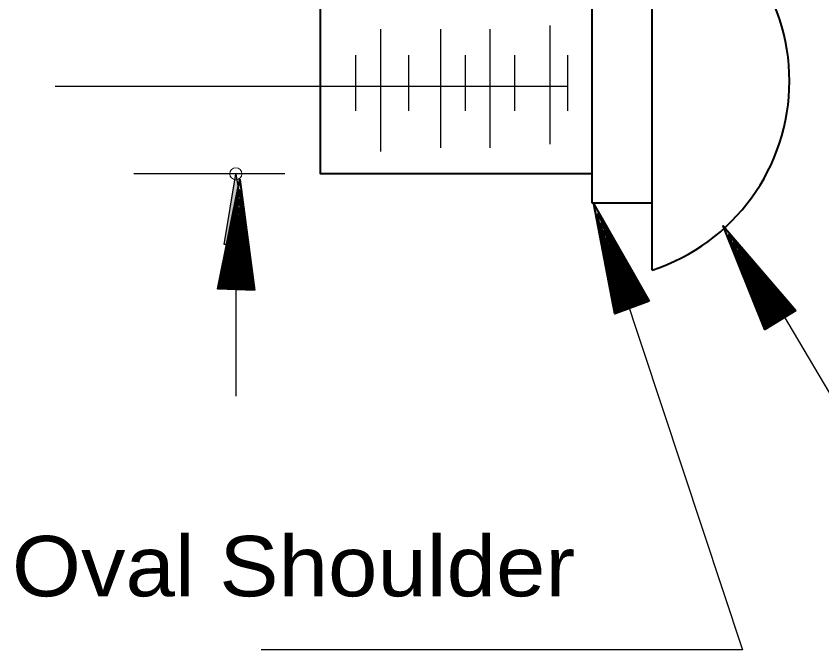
# Model space of a CAD drawing. Extents: x 895.6 to 930.4, y -2278.6 to -2254.7.
# Drawn here: x 902.343 to 904.058, y -2267.486 to -2266.136 of the extents above; entities that cross this region are included whole.
import ezdxf

# ---------------------------------------------------------------- set-up
doc = ezdxf.new("R2010")
doc.units = 0
doc.header["$LTSCALE"] = 0.051
doc.header["$PDMODE"] = 32
doc.header["$PDSIZE"] = 0.0255
for name, color, linetype, lineweight in [('1', 7, 'Continuous', 70), ('3', 7, 'Continuous', 40), ('6', 7, 'Continuous', 13)]:
    doc.layers.add(name, color=color, linetype=linetype, lineweight=lineweight)

msp = doc.modelspace()

# ---------------------------------------------------------------- hatches: boundary and pattern name
at = {"layer": '3'}
for points in [[(902.84975, -2266.71975), (902.77175, -2266.71708), (902.81867, -2266.48442), (902.81867, -2266.48442)], [(902.83533, -2266.62267), (902.78517, -2266.62267), (902.81025, -2266.472), (902.81025, -2266.472)], [(902.84583, -2266.7185), (902.77567, -2266.71617), (902.81783, -2266.50683), (902.81783, -2266.50683)], [(902.84233, -2266.7175), (902.77925, -2266.71533), (902.81725, -2266.52692), (902.81725, -2266.52692)], [(903.68983, -2266.74317), (903.61675, -2266.77033), (903.57225, -2266.53708), (903.57225, -2266.53708)], [(902.83925, -2266.7165), (902.7825, -2266.71458), (902.81667, -2266.545), (902.81667, -2266.545)], [(902.83658, -2266.71575), (902.78542, -2266.71392), (902.81617, -2266.56125), (902.81617, -2266.56125)], [(903.686, -2266.74358), (903.62, -2266.76783), (903.58, -2266.55833), (903.58, -2266.55833)], [(902.83392, -2266.71475), (902.78792, -2266.71325), (902.81567, -2266.57592), (902.81567, -2266.57592)], [(902.83158, -2266.71417), (902.79017, -2266.71283), (902.81517, -2266.58908), (902.81517, -2266.58908)], [(903.682, -2266.744), (903.623, -2266.76583), (903.587, -2266.57708), (903.587, -2266.57708)], [(904.00242, -2266.76292), (903.93608, -2266.80358), (903.84792, -2266.583), (903.84792, -2266.583)], [(902.82967, -2266.71342), (902.79233, -2266.71233), (902.81483, -2266.60108), (902.81483, -2266.60108)], [(903.67892, -2266.74425), (903.62575, -2266.76392), (903.59317, -2266.59383), (903.59317, -2266.59383)], [(903.99867, -2266.76408), (903.93883, -2266.80025), (903.85958, -2266.60225), (903.85958, -2266.60225)], [(902.82783, -2266.71308), (902.79417, -2266.71175), (902.81433, -2266.61167), (902.81433, -2266.61167)], [(902.82608, -2266.71242), (902.79575, -2266.71133), (902.81408, -2266.62133), (902.81408, -2266.62133)], [(903.67608, -2266.7445), (903.62817, -2266.76208), (903.599, -2266.60925), (903.599, -2266.60925)], [(903.67358, -2266.74442), (903.63025, -2266.7605), (903.604, -2266.62308), (903.604, -2266.62308)], [(903.99517, -2266.765), (903.94133, -2266.79783), (903.87, -2266.61925), (903.87, -2266.61925)], [(902.82458, -2266.71192), (902.79742, -2266.711), (902.81375, -2266.63), (902.81375, -2266.63)], [(902.82317, -2266.71158), (902.79883, -2266.71067), (902.81342, -2266.63775), (902.81342, -2266.63775)], [(903.67117, -2266.74483), (903.63208, -2266.75925), (903.60867, -2266.63517), (903.60867, -2266.63517)], [(903.99242, -2266.766), (903.94367, -2266.79542), (903.87925, -2266.63467), (903.87925, -2266.63467)], [(902.82208, -2266.71108), (902.8, -2266.71042), (902.81325, -2266.64492), (902.81325, -2266.64492)], [(902.82092, -2266.71067), (902.80108, -2266.71017), (902.81308, -2266.651), (902.81308, -2266.651)], [(902.82, -2266.71042), (902.80208, -2266.70983), (902.81292, -2266.65675), (902.81292, -2266.65675)], [(903.66908, -2266.74492), (903.634, -2266.75808), (903.61275, -2266.64667), (903.61275, -2266.64667)], [(903.66725, -2266.74542), (903.63558, -2266.757), (903.61625, -2266.65667), (903.61625, -2266.65667)], [(903.98958, -2266.76683), (903.94567, -2266.79325), (903.88792, -2266.64875), (903.88792, -2266.64875)], [(902.81908, -2266.71017), (902.80292, -2266.70975), (902.81258, -2266.66183), (902.81258, -2266.66183)], [(902.81825, -2266.70992), (902.80367, -2266.70942), (902.81242, -2266.66642), (902.81242, -2266.66642)], [(902.8175, -2266.70975), (902.8045, -2266.70933), (902.81233, -2266.6705), (902.81233, -2266.6705)], [(902.81708, -2266.70942), (902.80525, -2266.70917), (902.81233, -2266.67417), (902.81233, -2266.67417)], [(902.8165, -2266.70925), (902.80592, -2266.70892), (902.81225, -2266.67742), (902.81225, -2266.67742)], [(903.66542, -2266.74533), (903.63675, -2266.75575), (903.61958, -2266.66558), (903.61958, -2266.66558)], [(903.66383, -2266.74542), (903.63817, -2266.755), (903.62275, -2266.67367), (903.62275, -2266.67367)], [(903.98708, -2266.76717), (903.94742, -2266.79117), (903.8955, -2266.66133), (903.8955, -2266.66133)], [(903.98467, -2266.76808), (903.949, -2266.78967), (903.90233, -2266.67225), (903.90233, -2266.67225)], [(902.81617, -2266.709), (902.80658, -2266.70867), (902.81242, -2266.68042), (902.81242, -2266.68042)], [(902.81558, -2266.709), (902.80708, -2266.70867), (902.81225, -2266.68317), (902.81225, -2266.68317)], [(902.81508, -2266.70883), (902.8075, -2266.7085), (902.812, -2266.68558), (902.812, -2266.68558)], [(902.81483, -2266.70867), (902.808, -2266.70842), (902.81208, -2266.68775), (902.81208, -2266.68775)], [(903.66242, -2266.74575), (903.63933, -2266.75417), (903.62533, -2266.68125), (903.62533, -2266.68125)], [(903.66117, -2266.74542), (903.64042, -2266.75333), (903.62783, -2266.68767), (903.62783, -2266.68767)], [(903.66, -2266.74575), (903.64142, -2266.75267), (903.62992, -2266.69333), (903.62992, -2266.69333)], [(903.98258, -2266.7685), (903.95075, -2266.78808), (903.9085, -2266.68292), (903.9085, -2266.68292)], [(903.98075, -2266.76925), (903.952, -2266.78675), (903.914, -2266.692), (903.914, -2266.692)], [(903.659, -2266.74575), (903.64208, -2266.75217), (903.632, -2266.69892), (903.632, -2266.69892)], [(903.65808, -2266.74608), (903.64267, -2266.7515), (903.63367, -2266.70375), (903.63367, -2266.70375)], [(903.65725, -2266.74608), (903.64358, -2266.75108), (903.63517, -2266.70792), (903.63517, -2266.70792)], [(903.65642, -2266.746), (903.64433, -2266.75083), (903.6365, -2266.71175), (903.6365, -2266.71175)], [(903.97892, -2266.76975), (903.95283, -2266.78533), (903.91892, -2266.7), (903.91892, -2266.7)], [(903.97742, -2266.77), (903.95408, -2266.78425), (903.92342, -2266.70733), (903.92342, -2266.70733)], [(903.65583, -2266.74592), (903.64467, -2266.75033), (903.63825, -2266.71508), (903.63825, -2266.71508)], [(903.65525, -2266.74617), (903.64517, -2266.74967), (903.63908, -2266.71825), (903.63908, -2266.71825)], [(903.65492, -2266.746), (903.64575, -2266.74942), (903.64042, -2266.721), (903.64042, -2266.721)], [(903.65442, -2266.746), (903.64625, -2266.74917), (903.64142, -2266.72367), (903.64142, -2266.72367)], [(903.65383, -2266.74608), (903.6465, -2266.74883), (903.64208, -2266.726), (903.64208, -2266.726)], [(903.65358, -2266.74617), (903.64683, -2266.74833), (903.643, -2266.72783), (903.643, -2266.72783)], [(903.97617, -2266.7705), (903.95517, -2266.78325), (903.9275, -2266.7145), (903.9275, -2266.7145)], [(903.97492, -2266.7705), (903.95617, -2266.78217), (903.93117, -2266.72008), (903.93117, -2266.72008)], [(903.97383, -2266.77117), (903.957, -2266.78142), (903.93425, -2266.72542), (903.93425, -2266.72542)], [(903.97292, -2266.77125), (903.9575, -2266.78083), (903.93733, -2266.73042), (903.93733, -2266.73042)], [(903.97208, -2266.77158), (903.95783, -2266.78), (903.93992, -2266.73483), (903.93992, -2266.73483)], [(903.97133, -2266.772), (903.95858, -2266.77933), (903.94217, -2266.73867), (903.94217, -2266.73867)], [(903.9705, -2266.772), (903.95933, -2266.77908), (903.94425, -2266.74225), (903.94425, -2266.74225)], [(903.96992, -2266.77208), (903.95967, -2266.7785), (903.94667, -2266.745), (903.94667, -2266.745)], [(903.96933, -2266.77242), (903.96008, -2266.77775), (903.948, -2266.74817), (903.948, -2266.74817)], [(903.969, -2266.77233), (903.96058, -2266.77742), (903.94992, -2266.7505), (903.94992, -2266.7505)], [(903.9685, -2266.77242), (903.96108, -2266.77708), (903.95133, -2266.75283), (903.95133, -2266.75283)], [(903.96792, -2266.7725), (903.96125, -2266.77667), (903.9525, -2266.755), (903.9525, -2266.755)], [(903.96767, -2266.77258), (903.96142, -2266.77608), (903.95367, -2266.75683), (903.95367, -2266.75683)]]:
    msp.add_hatch(color=256, dxfattribs=at).paths.add_polyline_path(points)

# ---------------------------------------------------------------- linework, layer by layer
at = {"layer": '1', "lineweight": 40}
for p, q in [((903.69675, -2266.677), (903.69675, -2265.8725)), ((903.56908, -2266.53492), (903.56908, -2266.03817)), ((903.69675, -2266.53492), (903.56908, -2266.53492))]:
    msp.add_line(p, q, dxfattribs=at)
at = {"layer": '1', "lineweight": 25}
for p, q in [((903.47867, -2266.15658), (903.47867, -2266.40892)), ((903.118, -2266.16442), (903.118, -2266.42458)), ((903.24583, -2266.16442), (903.24583, -2266.41658)), ((903.351, -2266.16442), (903.351, -2266.41658)), ((903.06533, -2266.21967), (903.06533, -2266.33783)), ((903.17817, -2266.21967), (903.17817, -2266.33783)), ((903.2985, -2266.21967), (903.2985, -2266.33783)), ((903.40375, -2266.21967), (903.40375, -2266.33783)), ((903.51633, -2266.21967), (903.51633, -2266.33783))]:
    msp.add_line(p, q, dxfattribs=at)
at = {"layer": '1', "lineweight": 40}
msp.add_lwpolyline([(903.56908, -2266.472), (902.99017, -2266.472), (902.99017, -2266.10133)], dxfattribs=at)
msp.add_arc((903.56587, -2266.27472), 0.42298, 288.02436, 71.97563, dxfattribs=at)
at = {"layer": '3', "lineweight": 25}
for p, q in [((903.51633, -2266.28658), (902.4255, -2266.28658)), ((902.91483, -2266.472), (902.59342, -2266.472)), ((902.81025, -2266.62267), (902.81025, -2266.94517))]:
    msp.add_line(p, q, dxfattribs=at)
at = {"layer": '3'}
for points in [[(902.84975, -2266.71975), (902.77175, -2266.71708), (902.81867, -2266.48442), (902.81867, -2266.48442)], [(902.84583, -2266.7185), (902.77567, -2266.71617), (902.81783, -2266.50683), (902.81783, -2266.50683)], [(902.84233, -2266.7175), (902.77925, -2266.71533), (902.81725, -2266.52692), (902.81725, -2266.52692)], [(903.68983, -2266.74317), (903.61675, -2266.77033), (903.57225, -2266.53708), (903.57225, -2266.53708)], [(902.83925, -2266.7165), (902.7825, -2266.71458), (902.81667, -2266.545), (902.81667, -2266.545)], [(902.83658, -2266.71575), (902.78542, -2266.71392), (902.81617, -2266.56125), (902.81617, -2266.56125)], [(903.686, -2266.74358), (903.62, -2266.76783), (903.58, -2266.55833), (903.58, -2266.55833)], [(902.83392, -2266.71475), (902.78792, -2266.71325), (902.81567, -2266.57592), (902.81567, -2266.57592)], [(902.83158, -2266.71417), (902.79017, -2266.71283), (902.81517, -2266.58908), (902.81517, -2266.58908)], [(903.682, -2266.744), (903.623, -2266.76583), (903.587, -2266.57708), (903.587, -2266.57708)], [(904.00242, -2266.76292), (903.93608, -2266.80358), (903.84792, -2266.583), (903.84792, -2266.583)], [(902.82967, -2266.71342), (902.79233, -2266.71233), (902.81483, -2266.60108), (902.81483, -2266.60108)], [(903.67892, -2266.74425), (903.62575, -2266.76392), (903.59317, -2266.59383), (903.59317, -2266.59383)], [(903.99867, -2266.76408), (903.93883, -2266.80025), (903.85958, -2266.60225), (903.85958, -2266.60225)], [(902.82783, -2266.71308), (902.79417, -2266.71175), (902.81433, -2266.61167), (902.81433, -2266.61167)], [(902.82608, -2266.71242), (902.79575, -2266.71133), (902.81408, -2266.62133), (902.81408, -2266.62133)], [(903.67608, -2266.7445), (903.62817, -2266.76208), (903.599, -2266.60925), (903.599, -2266.60925)], [(903.67358, -2266.74442), (903.63025, -2266.7605), (903.604, -2266.62308), (903.604, -2266.62308)], [(903.99517, -2266.765), (903.94133, -2266.79783), (903.87, -2266.61925), (903.87, -2266.61925)], [(902.82458, -2266.71192), (902.79742, -2266.711), (902.81375, -2266.63), (902.81375, -2266.63)], [(902.82317, -2266.71158), (902.79883, -2266.71067), (902.81342, -2266.63775), (902.81342, -2266.63775)], [(903.67117, -2266.74483), (903.63208, -2266.75925), (903.60867, -2266.63517), (903.60867, -2266.63517)], [(903.99242, -2266.766), (903.94367, -2266.79542), (903.87925, -2266.63467), (903.87925, -2266.63467)], [(902.82208, -2266.71108), (902.8, -2266.71042), (902.81325, -2266.64492), (902.81325, -2266.64492)], [(902.82092, -2266.71067), (902.80108, -2266.71017), (902.81308, -2266.651), (902.81308, -2266.651)], [(902.82, -2266.71042), (902.80208, -2266.70983), (902.81292, -2266.65675), (902.81292, -2266.65675)], [(903.66908, -2266.74492), (903.634, -2266.75808), (903.61275, -2266.64667), (903.61275, -2266.64667)], [(903.66725, -2266.74542), (903.63558, -2266.757), (903.61625, -2266.65667), (903.61625, -2266.65667)], [(903.98958, -2266.76683), (903.94567, -2266.79325), (903.88792, -2266.64875), (903.88792, -2266.64875)], [(902.81908, -2266.71017), (902.80292, -2266.70975), (902.81258, -2266.66183), (902.81258, -2266.66183)], [(902.81825, -2266.70992), (902.80367, -2266.70942), (902.81242, -2266.66642), (902.81242, -2266.66642)], [(902.8175, -2266.70975), (902.8045, -2266.70933), (902.81233, -2266.6705), (902.81233, -2266.6705)], [(902.81708, -2266.70942), (902.80525, -2266.70917), (902.81233, -2266.67417), (902.81233, -2266.67417)], [(902.8165, -2266.70925), (902.80592, -2266.70892), (902.81225, -2266.67742), (902.81225, -2266.67742)], [(903.66542, -2266.74533), (903.63675, -2266.75575), (903.61958, -2266.66558), (903.61958, -2266.66558)], [(903.66383, -2266.74542), (903.63817, -2266.755), (903.62275, -2266.67367), (903.62275, -2266.67367)], [(903.98708, -2266.76717), (903.94742, -2266.79117), (903.8955, -2266.66133), (903.8955, -2266.66133)], [(903.98467, -2266.76808), (903.949, -2266.78967), (903.90233, -2266.67225), (903.90233, -2266.67225)], [(902.81617, -2266.709), (902.80658, -2266.70867), (902.81242, -2266.68042), (902.81242, -2266.68042)], [(902.81558, -2266.709), (902.80708, -2266.70867), (902.81225, -2266.68317), (902.81225, -2266.68317)], [(902.81508, -2266.70883), (902.8075, -2266.7085), (902.812, -2266.68558), (902.812, -2266.68558)], [(902.81483, -2266.70867), (902.808, -2266.70842), (902.81208, -2266.68775), (902.81208, -2266.68775)], [(903.66242, -2266.74575), (903.63933, -2266.75417), (903.62533, -2266.68125), (903.62533, -2266.68125)], [(903.66117, -2266.74542), (903.64042, -2266.75333), (903.62783, -2266.68767), (903.62783, -2266.68767)], [(903.66, -2266.74575), (903.64142, -2266.75267), (903.62992, -2266.69333), (903.62992, -2266.69333)], [(903.98258, -2266.7685), (903.95075, -2266.78808), (903.9085, -2266.68292), (903.9085, -2266.68292)], [(903.98075, -2266.76925), (903.952, -2266.78675), (903.914, -2266.692), (903.914, -2266.692)], [(903.659, -2266.74575), (903.64208, -2266.75217), (903.632, -2266.69892), (903.632, -2266.69892)], [(903.65808, -2266.74608), (903.64267, -2266.7515), (903.63367, -2266.70375), (903.63367, -2266.70375)], [(903.65725, -2266.74608), (903.64358, -2266.75108), (903.63517, -2266.70792), (903.63517, -2266.70792)], [(903.65642, -2266.746), (903.64433, -2266.75083), (903.6365, -2266.71175), (903.6365, -2266.71175)], [(903.97892, -2266.76975), (903.95283, -2266.78533), (903.91892, -2266.7), (903.91892, -2266.7)], [(903.97742, -2266.77), (903.95408, -2266.78425), (903.92342, -2266.70733), (903.92342, -2266.70733)], [(903.65583, -2266.74592), (903.64467, -2266.75033), (903.63825, -2266.71508), (903.63825, -2266.71508)], [(903.65525, -2266.74617), (903.64517, -2266.74967), (903.63908, -2266.71825), (903.63908, -2266.71825)], [(903.65492, -2266.746), (903.64575, -2266.74942), (903.64042, -2266.721), (903.64042, -2266.721)], [(903.65442, -2266.746), (903.64625, -2266.74917), (903.64142, -2266.72367), (903.64142, -2266.72367)], [(903.65383, -2266.74608), (903.6465, -2266.74883), (903.64208, -2266.726), (903.64208, -2266.726)], [(903.65358, -2266.74617), (903.64683, -2266.74833), (903.643, -2266.72783), (903.643, -2266.72783)], [(903.97617, -2266.7705), (903.95517, -2266.78325), (903.9275, -2266.7145), (903.9275, -2266.7145)], [(903.97492, -2266.7705), (903.95617, -2266.78217), (903.93117, -2266.72008), (903.93117, -2266.72008)], [(903.97383, -2266.77117), (903.957, -2266.78142), (903.93425, -2266.72542), (903.93425, -2266.72542)], [(903.97292, -2266.77125), (903.9575, -2266.78083), (903.93733, -2266.73042), (903.93733, -2266.73042)], [(903.97208, -2266.77158), (903.95783, -2266.78), (903.93992, -2266.73483), (903.93992, -2266.73483)], [(903.97133, -2266.772), (903.95858, -2266.77933), (903.94217, -2266.73867), (903.94217, -2266.73867)], [(903.9705, -2266.772), (903.95933, -2266.77908), (903.94425, -2266.74225), (903.94425, -2266.74225)], [(903.96992, -2266.77208), (903.95967, -2266.7785), (903.94667, -2266.745), (903.94667, -2266.745)], [(903.96933, -2266.77242), (903.96008, -2266.77775), (903.948, -2266.74817), (903.948, -2266.74817)], [(903.969, -2266.77233), (903.96058, -2266.77742), (903.94992, -2266.7505), (903.94992, -2266.7505)], [(903.9685, -2266.77242), (903.96108, -2266.77708), (903.95133, -2266.75283), (903.95133, -2266.75283)], [(903.96792, -2266.7725), (903.96125, -2266.77667), (903.9525, -2266.755), (903.9525, -2266.755)], [(903.96767, -2266.77258), (903.96142, -2266.77608), (903.95367, -2266.75683), (903.95367, -2266.75683)]]:
    msp.add_lwpolyline(points, close=True, dxfattribs=at)
at = {"layer": '3', "lineweight": 25}
msp.add_lwpolyline([(902.83533, -2266.62267), (902.78517, -2266.62267), (902.81025, -2266.472), (902.81025, -2266.472)], close=True, dxfattribs=at)
for points in [[(903.63292, -2266.71292), (903.88875, -2267.48558), (902.86442, -2267.48558)], [(903.97417, -2266.77058), (904.16275, -2267.08892), (906.13633, -2267.08892)]]:
    msp.add_lwpolyline(points, dxfattribs=at)
at = {"layer": '6'}
msp.add_line((902.99017, -2266.472), (902.99033, -2266.472), dxfattribs=at)
msp.add_point((902.81025, -2266.472), dxfattribs=at)

# ---------------------------------------------------------------- texts
at = {"layer": '3', "width": 1.1}
msp.add_text('Oval Shoulder', height=0.1286, dxfattribs=at).set_placement((902.33358, -2267.37158))

doc.saveas('drawing.dxf')
